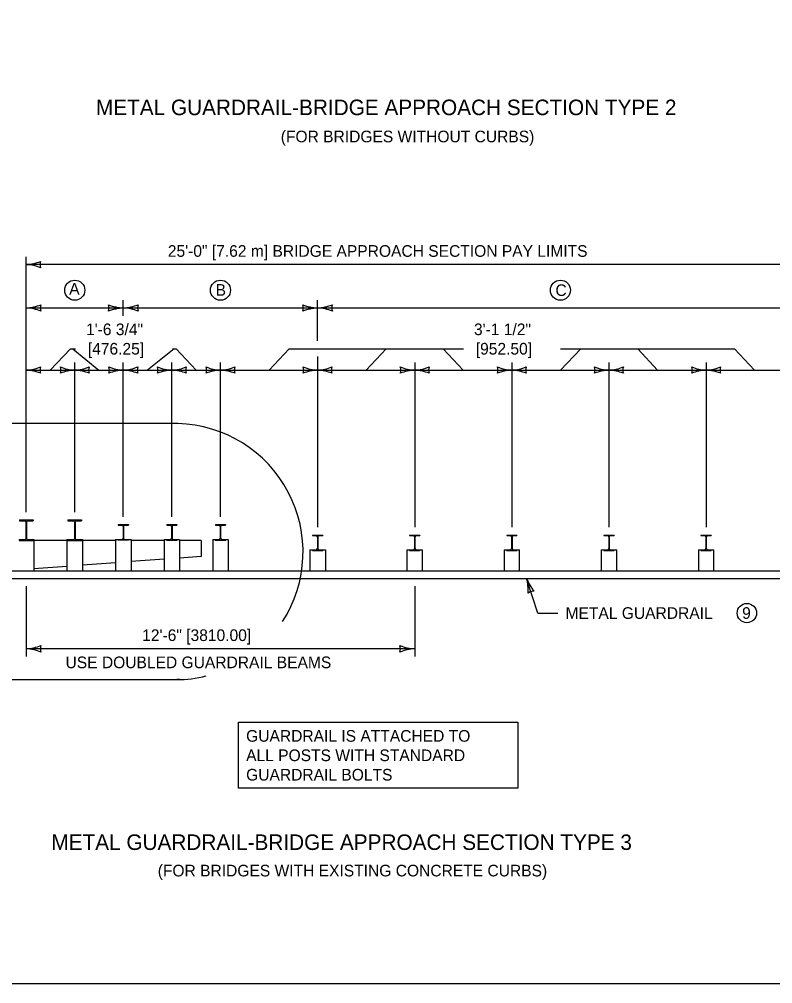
# Model space of a CAD drawing. Extents: x 49991.4 to 50021, y 49987.6 to 50011.4.
# Drawn here: x 50009.666 to 50013.547, y 49987.799 to 49992.766 of the extents above; entities that cross this region are included whole.
import ezdxf

# ---------------------------------------------------------------- set-up
doc = ezdxf.new("R2010")
doc.units = 0
for name, color, linetype in [('Level 1', 7, 'Continuous'), ('Level 2', 7, 'Continuous'), ('Level 3', 7, 'Continuous'), ('Level 4', 7, 'Continuous')]:
    doc.layers.add(name, color=color, linetype=linetype)

msp = doc.modelspace()

# ---------------------------------------------------------------- linework, layer by layer
at = {"layer": 'Level 1'}
for p, q in [((50009.6668, 49990.1875), (50009.7371, 49990.1875)), ((50009.6668, 49990.1875), (50009.6668, 49990.1822)), ((50009.7371, 49990.1875), (50009.7371, 49990.1822)), ((50009.9169, 49990.1875), (50009.9872, 49990.1875)), ((50009.9169, 49990.1875), (50009.9169, 49990.1822)), ((50009.9872, 49990.1875), (50009.9872, 49990.1822)), ((50009.6668, 49990.1822), (50009.6956, 49990.1822)), ((50009.7003, 49990.1775), (50009.7003, 49990.0908)), ((50009.7036, 49990.1775), (50009.7036, 49990.0908)), ((50009.7083, 49990.1822), (50009.7371, 49990.1822)), ((50009.9169, 49990.1822), (50009.9457, 49990.1822)), ((50009.9504, 49990.1775), (50009.9504, 49990.0908)), ((50009.9537, 49990.1775), (50009.9537, 49990.0908)), ((50009.9584, 49990.1822), (50009.9872, 49990.1822)), ((50010.1759, 49990.1633), (50010.2285, 49990.1633)), ((50010.1759, 49990.1633), (50010.1759, 49990.1604)), ((50010.1759, 49990.1604), (50010.1939, 49990.1604)), ((50010.2011, 49990.1533), (50010.2011, 49990.0932)), ((50010.2033, 49990.1533), (50010.2033, 49990.0932)), ((50010.2105, 49990.1604), (50010.2285, 49990.1604)), ((50010.2285, 49990.1633), (50010.2285, 49990.1604)), ((50010.4261, 49990.1633), (50010.4786, 49990.1633)), ((50010.4261, 49990.1633), (50010.4261, 49990.1604)), ((50010.4261, 49990.1604), (50010.4441, 49990.1604)), ((50010.4512, 49990.1533), (50010.4512, 49990.0932)), ((50010.4535, 49990.1533), (50010.4535, 49990.0932)), ((50010.4606, 49990.1604), (50010.4786, 49990.1604)), ((50010.4786, 49990.1633), (50010.4786, 49990.1604)), ((50010.6762, 49990.1633), (50010.7288, 49990.1633)), ((50010.6762, 49990.1633), (50010.6762, 49990.1604)), ((50010.6762, 49990.1604), (50010.6942, 49990.1604)), ((50010.7014, 49990.1533), (50010.7014, 49990.0932)), ((50010.7036, 49990.1533), (50010.7036, 49990.0932)), ((50010.7108, 49990.1604), (50010.7288, 49990.1604)), ((50010.7288, 49990.1633), (50010.7288, 49990.1604)), ((50009.6668, 49990.0808), (50009.6668, 49990.0861)), ((50009.6668, 49990.0861), (50009.6956, 49990.0861)), ((50009.7083, 49990.0861), (50009.7371, 49990.0861)), ((50009.7371, 49990.0808), (50009.7371, 49990.0861)), ((50009.7377, 49990.0808), (50009.7377, 49990.0861)), ((50009.7377, 49990.0861), (50009.742, 49990.0861)), ((50009.742, 49990.0861), (50009.742, 49989.9261)), ((50009.912, 49990.0861), (50009.912, 49989.9261)), ((50009.912, 49990.0861), (50009.9162, 49990.0861)), ((50009.9162, 49990.0808), (50009.9162, 49990.0861)), ((50009.9169, 49990.0808), (50009.9169, 49990.0861)), ((50009.9169, 49990.0861), (50009.9457, 49990.0861)), ((50009.9584, 49990.0861), (50009.9872, 49990.0861)), ((50009.9872, 49990.0808), (50009.9872, 49990.0861)), ((50009.9879, 49990.0808), (50009.9879, 49990.0861)), ((50009.9879, 49990.0861), (50009.9921, 49990.0861)), ((50009.9921, 49990.0861), (50009.9921, 49989.9261)), ((50010.1622, 49990.0861), (50010.1622, 49989.9261)), ((50010.1622, 49990.0861), (50010.1752, 49990.0861)), ((50010.1752, 49990.0832), (50010.1752, 49990.0861)), ((50010.2291, 49990.0832), (50010.1752, 49990.0832)), ((50010.1759, 49990.0832), (50010.1759, 49990.0861)), ((50010.1759, 49990.0861), (50010.1939, 49990.0861)), ((50010.2105, 49990.0861), (50010.2285, 49990.0861)), ((50010.2285, 49990.0832), (50010.2285, 49990.0861)), ((50010.2291, 49990.0832), (50010.2291, 49990.0861)), ((50010.2291, 49990.0861), (50010.2422, 49990.0861)), ((50010.2422, 49990.0861), (50010.2422, 49989.9261)), ((50010.4123, 49990.0861), (50010.4123, 49989.9261)), ((50010.4123, 49990.0861), (50010.4254, 49990.0861)), ((50010.4254, 49990.0832), (50010.4254, 49990.0861)), ((50010.4254, 49990.0832), (50010.4793, 49990.0832)), ((50010.4261, 49990.0832), (50010.4261, 49990.0861)), ((50010.4261, 49990.0861), (50010.4441, 49990.0861)), ((50010.4606, 49990.0861), (50010.4786, 49990.0861)), ((50010.4786, 49990.0832), (50010.4786, 49990.0861)), ((50010.4793, 49990.0832), (50010.4793, 49990.0861)), ((50010.4793, 49990.0861), (50010.4924, 49990.0861)), ((50010.4924, 49990.0861), (50010.4924, 49989.9261)), ((50010.6625, 49990.0861), (50010.6625, 49989.9261)), ((50010.6625, 49990.0861), (50010.6756, 49990.0861)), ((50010.6756, 49990.0832), (50010.6756, 49990.0861)), ((50010.6756, 49990.0832), (50010.7294, 49990.0832)), ((50010.6762, 49990.0832), (50010.6762, 49990.0861)), ((50010.6762, 49990.0861), (50010.6942, 49990.0861)), ((50010.7108, 49990.0861), (50010.7288, 49990.0861)), ((50010.7288, 49990.0832), (50010.7288, 49990.0861)), ((50010.7294, 49990.0832), (50010.7294, 49990.0861)), ((50010.7294, 49990.0861), (50010.7425, 49990.0861)), ((50010.7425, 49990.0861), (50010.7425, 49989.9261)), ((50011.1765, 49990.1099), (50011.229, 49990.1099)), ((50011.1765, 49990.1099), (50011.1765, 49990.1071)), ((50011.1765, 49990.1071), (50011.1945, 49990.1071)), ((50011.2016, 49990.0999), (50011.2016, 49990.0399)), ((50011.2039, 49990.0999), (50011.2039, 49990.0399)), ((50011.211, 49990.1071), (50011.229, 49990.1071)), ((50011.229, 49990.1099), (50011.229, 49990.1071)), ((50011.6767, 49990.1099), (50011.7293, 49990.1099)), ((50011.6767, 49990.1099), (50011.6767, 49990.1071)), ((50011.6767, 49990.1071), (50011.6948, 49990.1071)), ((50011.7019, 49990.0999), (50011.7019, 49990.0399)), ((50011.7042, 49990.0999), (50011.7042, 49990.0399)), ((50011.7113, 49990.1071), (50011.7293, 49990.1071)), ((50011.7293, 49990.1099), (50011.7293, 49990.1071)), ((50012.177, 49990.1099), (50012.2296, 49990.1099)), ((50012.177, 49990.1099), (50012.177, 49990.1071)), ((50012.177, 49990.1071), (50012.195, 49990.1071)), ((50012.2021, 49990.0999), (50012.2021, 49990.0399)), ((50012.2044, 49990.0999), (50012.2044, 49990.0399)), ((50012.2115, 49990.1071), (50012.2296, 49990.1071)), ((50012.2296, 49990.1099), (50012.2296, 49990.1071)), ((50012.6773, 49990.1099), (50012.7298, 49990.1099)), ((50012.6773, 49990.1099), (50012.6773, 49990.1071)), ((50012.6773, 49990.1071), (50012.6953, 49990.1071)), ((50012.7024, 49990.0999), (50012.7024, 49990.0399)), ((50012.7047, 49990.0999), (50012.7047, 49990.0399)), ((50012.7118, 49990.1071), (50012.7298, 49990.1071)), ((50012.7298, 49990.1099), (50012.7298, 49990.1071)), ((50013.1775, 49990.1099), (50013.2301, 49990.1099)), ((50013.1775, 49990.1099), (50013.1775, 49990.1071)), ((50013.1775, 49990.1071), (50013.1955, 49990.1071)), ((50013.2027, 49990.0999), (50013.2027, 49990.0399)), ((50013.2049, 49990.0999), (50013.2049, 49990.0399)), ((50013.2121, 49990.1071), (50013.2301, 49990.1071)), ((50013.2301, 49990.1099), (50013.2301, 49990.1071)), ((50009.6661, 49990.0808), (50009.7377, 49990.0808)), ((50009.912, 49990.0808), (50009.742, 49990.0808)), ((50009.9162, 49990.0808), (50009.9879, 49990.0808)), ((50010.1622, 49990.0808), (50009.9921, 49990.0808)), ((50010.4123, 49990.0808), (50010.2422, 49990.0808)), ((50010.6033, 49990.0808), (50010.4924, 49990.0808)), ((50010.6033, 49990.0808), (50010.6033, 49989.9994)), ((50010.4123, 49989.9853), (50010.2422, 49989.9727)), ((50010.6033, 49989.9994), (50010.4924, 49989.9912)), ((50011.1627, 49990.0328), (50011.1627, 49989.9261)), ((50011.1627, 49990.0328), (50011.1758, 49990.0328)), ((50011.1758, 49990.0299), (50011.1758, 49990.0328)), ((50011.1758, 49990.0299), (50011.2297, 49990.0299)), ((50011.1765, 49990.0299), (50011.1765, 49990.0328)), ((50011.1765, 49990.0328), (50011.1945, 49990.0328)), ((50011.211, 49990.0328), (50011.229, 49990.0328)), ((50011.229, 49990.0299), (50011.229, 49990.0328)), ((50011.2297, 49990.0299), (50011.2297, 49990.0328)), ((50011.2297, 49990.0328), (50011.2428, 49990.0328)), ((50011.2428, 49990.0328), (50011.2428, 49989.9261)), ((50011.663, 49990.0328), (50011.663, 49989.9261)), ((50011.663, 49990.0328), (50011.6761, 49990.0328)), ((50011.6761, 49990.0299), (50011.6761, 49990.0328)), ((50011.6761, 49990.0299), (50011.73, 49990.0299)), ((50011.6767, 49990.0299), (50011.6767, 49990.0328)), ((50011.6767, 49990.0328), (50011.6948, 49990.0328)), ((50011.7113, 49990.0328), (50011.7293, 49990.0328)), ((50011.7293, 49990.0299), (50011.7293, 49990.0328)), ((50011.73, 49990.0299), (50011.73, 49990.0328)), ((50011.73, 49990.0328), (50011.743, 49990.0328)), ((50011.743, 49989.9261), (50011.743, 49990.0328)), ((50012.1633, 49990.0328), (50012.1633, 49989.9261)), ((50012.1633, 49990.0328), (50012.1763, 49990.0328)), ((50012.1763, 49990.0299), (50012.1763, 49990.0328)), ((50012.1763, 49990.0299), (50012.2302, 49990.0299)), ((50012.177, 49990.0299), (50012.177, 49990.0328)), ((50012.177, 49990.0328), (50012.195, 49990.0328)), ((50012.2115, 49990.0328), (50012.2296, 49990.0328)), ((50012.2296, 49990.0299), (50012.2296, 49990.0328)), ((50012.2302, 49990.0299), (50012.2302, 49990.0328)), ((50012.2302, 49990.0328), (50012.2433, 49990.0328)), ((50012.2433, 49989.9261), (50012.2433, 49990.0328)), ((50012.6635, 49990.0328), (50012.6635, 49989.9261)), ((50012.6635, 49990.0328), (50012.6766, 49990.0328)), ((50012.6766, 49990.0299), (50012.6766, 49990.0328)), ((50012.6766, 49990.0299), (50012.7305, 49990.0299)), ((50012.6773, 49990.0299), (50012.6773, 49990.0328)), ((50012.6773, 49990.0328), (50012.6953, 49990.0328)), ((50012.7118, 49990.0328), (50012.7298, 49990.0328)), ((50012.7298, 49990.0299), (50012.7298, 49990.0328)), ((50012.7305, 49990.0299), (50012.7305, 49990.0328)), ((50012.7305, 49990.0328), (50012.7436, 49990.0328)), ((50012.7436, 49989.9261), (50012.7436, 49990.0328)), ((50013.1638, 49990.0328), (50013.1638, 49989.9261)), ((50013.1638, 49990.0328), (50013.1769, 49990.0328)), ((50013.1769, 49990.0299), (50013.1769, 49990.0328)), ((50013.1769, 49990.0299), (50013.2307, 49990.0299)), ((50013.1775, 49990.0299), (50013.1775, 49990.0328)), ((50013.1775, 49990.0328), (50013.1955, 49990.0328)), ((50013.2121, 49990.0328), (50013.2301, 49990.0328)), ((50013.2301, 49990.0299), (50013.2301, 49990.0328)), ((50013.2307, 49990.0299), (50013.2307, 49990.0328)), ((50013.2307, 49990.0328), (50013.2438, 49990.0328)), ((50013.2438, 49989.9261), (50013.2438, 49990.0328)), ((50009.912, 49989.9482), (50009.742, 49989.9356)), ((50010.1622, 49989.9667), (50009.9921, 49989.9541)), ((50008.8185, 49989.9261), (50013.9981, 49989.9261)), ((50008.8185, 49989.886), (50013.9981, 49989.886))]:
    msp.add_line(p, q, dxfattribs=at)
msp.add_lwpolyline([(49999.3835, 49998.9992), (50016.7501, 49998.9992), (50016.7501, 49987.7988), (49999.3835, 49987.7988)], close=True, dxfattribs=at)
msp.add_circle((50013.4138, 49989.7079), 0.05, dxfattribs=at)
for centre, radius, start, end in [((50009.6956, 49990.1775), 0.00467, 0, 90), ((50009.7083, 49990.1775), 0.00467, 90, 180), ((50009.9457, 49990.1775), 0.00467, 0, 90), ((50009.9584, 49990.1775), 0.00467, 90, 180), ((50010.1939, 49990.1533), 0.00714, 0, 90), ((50010.2105, 49990.1533), 0.00714, 90, 180), ((50010.4441, 49990.1533), 0.00714, 0, 90), ((50010.4606, 49990.1533), 0.00714, 90, 180), ((50010.6942, 49990.1533), 0.00714, 0, 90), ((50010.7108, 49990.1533), 0.00714, 90, 180), ((50009.6956, 49990.0908), 0.00467, 270, 0), ((50009.7083, 49990.0908), 0.00467, 180, 270), ((50009.9457, 49990.0908), 0.00467, 270, 0), ((50009.9584, 49990.0908), 0.00467, 180, 270), ((50010.1939, 49990.0932), 0.00714, 270, 0), ((50010.2105, 49990.0932), 0.00714, 180, 270), ((50010.4441, 49990.0932), 0.00714, 270, 0), ((50010.4606, 49990.0932), 0.00714, 180, 270), ((50010.6942, 49990.0932), 0.00714, 270, 0), ((50010.7108, 49990.0932), 0.00714, 180, 270), ((50011.1945, 49990.0999), 0.00714, 0, 90), ((50011.211, 49990.0999), 0.00714, 90, 180), ((50011.6948, 49990.0999), 0.00714, 0, 90), ((50011.7113, 49990.0999), 0.00714, 90, 180), ((50012.195, 49990.0999), 0.00714, 0, 90), ((50012.2115, 49990.0999), 0.00714, 90, 180), ((50012.6953, 49990.0999), 0.00714, 0, 90), ((50012.7118, 49990.0999), 0.00714, 90, 180), ((50013.1955, 49990.0999), 0.00714, 0, 90), ((50013.2121, 49990.0999), 0.00714, 90, 180), ((50011.1945, 49990.0399), 0.00714, 270, 0), ((50011.211, 49990.0399), 0.00714, 180, 270), ((50011.6948, 49990.0399), 0.00714, 270, 0), ((50011.7113, 49990.0399), 0.00714, 180, 270), ((50012.195, 49990.0399), 0.00714, 270, 0), ((50012.2115, 49990.0399), 0.00714, 180, 270), ((50012.6953, 49990.0399), 0.00714, 270, 0), ((50012.7118, 49990.0399), 0.00714, 180, 270), ((50013.1955, 49990.0399), 0.00714, 270, 0), ((50013.2121, 49990.0399), 0.00714, 180, 270)]:
    msp.add_arc(centre, radius, start, end, dxfattribs=at)
at = {"layer": 'Level 2'}
for p, q in [((50010.7948, 49988.8052), (50010.7948, 49989.1452)), ((50010.7948, 49989.1452), (50012.2345, 49989.1452)), ((50012.2345, 49989.1452), (50012.2345, 49988.8052)), ((50012.2345, 49988.8052), (50010.7948, 49988.8052))]:
    msp.add_line(p, q, dxfattribs=at)
for centre in [(50009.9521, 49991.3709), (50010.7025, 49991.3709), (50012.4534, 49991.3709)]:
    msp.add_circle(centre, 0.0517, dxfattribs=at)
at = {"layer": 'Level 3'}
for p, q in [((50009.702, 49990.2275), (50009.702, 49991.5426)), ((50014.6522, 49991.5026), (50009.702, 49991.5026)), ((50009.702, 49991.2792), (50010.2022, 49991.2792)), ((50010.2022, 49991.2392), (50010.2022, 49991.3192)), ((50010.2022, 49991.2792), (50011.2028, 49991.2792)), ((50011.2028, 49991.1092), (50011.2028, 49991.3192)), ((50011.2028, 49991.2792), (50013.7041, 49991.2792)), ((50009.9295, 49991.0692), (50009.8261, 49990.9592)), ((50009.9295, 49991.0692), (50009.9555, 49991.0692)), ((50009.9425, 49991.0692), (50010.0762, 49990.9592)), ((50010.4644, 49991.0692), (50010.327, 49990.9592)), ((50010.4551, 49991.0692), (50010.4737, 49991.0692)), ((50010.4737, 49991.0692), (50010.5771, 49990.9592)), ((50011.0559, 49991.0692), (50010.9526, 49990.9592)), ((50011.0559, 49991.0692), (50011.4417, 49991.0692)), ((50011.2027, 49991.0292), (50011.2027, 49990.1499)), ((50011.4417, 49991.0692), (50011.9536, 49991.0692)), ((50011.5562, 49991.0692), (50011.4529, 49990.9592)), ((50011.8497, 49991.0692), (50011.9531, 49990.9592)), ((50012.4532, 49991.0692), (50012.741, 49991.0692)), ((50012.5585, 49991.0692), (50012.4534, 49990.9592)), ((50012.741, 49991.0692), (50013.3501, 49991.0692)), ((50012.8517, 49991.0692), (50012.9537, 49990.9592)), ((50013.3501, 49991.0692), (50013.4535, 49990.9592)), ((50009.9521, 49990.2275), (50009.9521, 49990.9992)), ((50010.2022, 49990.2033), (50010.2022, 49990.9992)), ((50010.4524, 49990.2033), (50010.4523, 49990.9992)), ((50010.7025, 49990.2033), (50010.7024, 49990.9992)), ((50011.703, 49990.9992), (50011.703, 49990.1499)), ((50012.2033, 49990.9992), (50012.2033, 49990.1499)), ((50012.7035, 49990.9992), (50012.7035, 49990.1499)), ((50013.2038, 49990.9992), (50013.2038, 49990.1499)), ((50009.702, 49990.9592), (50013.7041, 49990.9592)), ((50012.3374, 49989.7079), (50012.2794, 49989.886)), ((50009.702, 49989.8461), (50009.702, 49989.4839)), ((50011.7031, 49989.8461), (50011.7031, 49989.4839)), ((50012.3374, 49989.7079), (50012.4398, 49989.7079)), ((50011.7031, 49989.5239), (50009.702, 49989.5239))]:
    msp.add_line(p, q, dxfattribs=at)
for centre, radius, start, end in [((50009.6908, 49991.7295), 0.2271, 272.8273, 292.0772), ((50009.693, 49991.2861), 0.2167, 67.456, 87.6395), ((50009.8269, 49991.5026), 0.0534, 162.1388, 197.8612), ((50009.6905, 49991.512), 0.2331, 272.8273, 292.0772), ((50009.6928, 49991.0569), 0.2224, 67.456, 87.6395), ((50009.8302, 49991.2792), 0.0548, 162.1388, 197.8612), ((50010.2114, 49991.5014), 0.2224, 247.456, 267.6395), ((50010.0739, 49991.2792), 0.0548, 342.1388, 17.8612), ((50010.2137, 49991.0463), 0.2331, 92.8273, 112.0772), ((50010.1907, 49991.512), 0.2331, 272.8273, 292.0772), ((50010.1931, 49991.0569), 0.2224, 67.456, 87.6395), ((50010.3305, 49991.2792), 0.0548, 162.1388, 197.8612), ((50011.212, 49991.5014), 0.2224, 247.456, 267.6395), ((50011.0745, 49991.2792), 0.0548, 342.1388, 17.8612), ((50011.2143, 49991.0463), 0.2331, 92.8273, 112.0772), ((50011.1913, 49991.512), 0.2331, 272.8273, 292.0772), ((50011.1936, 49991.0569), 0.2224, 67.456, 87.6395), ((50011.3311, 49991.2792), 0.0548, 162.1388, 197.8612), ((50009.6908, 49991.186), 0.2271, 272.8273, 292.0772), ((50009.693, 49990.7426), 0.2167, 67.456, 87.6395), ((50009.8269, 49990.9592), 0.0534, 162.1388, 197.8612), ((50009.961, 49991.1757), 0.2167, 247.456, 267.6395), ((50009.8271, 49990.9592), 0.0534, 342.1388, 17.8612), ((50009.9633, 49990.7323), 0.2271, 92.8273, 112.0772), ((50009.9409, 49991.186), 0.2271, 272.8273, 292.0772), ((50009.9432, 49990.7426), 0.2167, 67.456, 87.6395), ((50010.0771, 49990.9592), 0.0534, 162.1388, 197.8612), ((50010.2111, 49991.1757), 0.2167, 247.456, 267.6395), ((50010.0772, 49990.9592), 0.0534, 342.1388, 17.8612), ((50010.2134, 49990.7323), 0.2271, 92.8273, 112.0772), ((50010.191, 49991.186), 0.2271, 272.8273, 292.0772), ((50010.1933, 49990.7426), 0.2167, 67.456, 87.6395), ((50010.3272, 49990.9592), 0.0534, 162.1388, 197.8612), ((50010.4612, 49991.1757), 0.2167, 247.456, 267.6395), ((50010.3273, 49990.9592), 0.0534, 342.1388, 17.8612), ((50010.4635, 49990.7323), 0.2271, 92.8273, 112.0772), ((50010.4411, 49991.186), 0.2271, 272.8273, 292.0772), ((50010.4434, 49990.7426), 0.2167, 67.456, 87.6395), ((50010.5773, 49990.9592), 0.0534, 162.1388, 197.8612), ((50010.7114, 49991.1757), 0.2167, 247.456, 267.6395), ((50010.5775, 49990.9592), 0.0534, 342.1388, 17.8612), ((50010.7136, 49990.7323), 0.2271, 92.8273, 112.0772), ((50010.6912, 49991.186), 0.2271, 272.8273, 292.0772), ((50010.6935, 49990.7426), 0.2167, 67.456, 87.6395), ((50010.8274, 49990.9592), 0.0534, 162.1388, 197.8612), ((50011.2117, 49991.1757), 0.2167, 247.456, 267.6395), ((50011.0778, 49990.9592), 0.0534, 342.1388, 17.8612), ((50011.2139, 49990.7323), 0.2271, 92.8273, 112.0772), ((50011.1915, 49991.186), 0.2271, 272.8273, 292.0772), ((50011.1938, 49990.7426), 0.2167, 67.456, 87.6395), ((50011.3277, 49990.9592), 0.0534, 162.1388, 197.8612), ((50011.7119, 49991.1757), 0.2167, 247.456, 267.6395), ((50011.578, 49990.9592), 0.0534, 342.1388, 17.8612), ((50011.7142, 49990.7323), 0.2271, 92.8273, 112.0772), ((50011.6918, 49991.186), 0.2271, 272.8273, 292.0772), ((50011.6941, 49990.7426), 0.2167, 67.456, 87.6395), ((50011.828, 49990.9592), 0.0534, 162.1388, 197.8612), ((50012.2122, 49991.1757), 0.2167, 247.456, 267.6395), ((50012.0783, 49990.9592), 0.0534, 342.1388, 17.8612), ((50012.2145, 49990.7323), 0.2271, 92.8273, 112.0772), ((50012.1921, 49991.186), 0.2271, 272.8273, 292.0772), ((50012.1943, 49990.7426), 0.2167, 67.456, 87.6395), ((50012.3283, 49990.9592), 0.0534, 162.1388, 197.8612), ((50012.7125, 49991.1757), 0.2167, 247.456, 267.6395), ((50012.5786, 49990.9592), 0.0534, 342.1388, 17.8612), ((50012.7147, 49990.7323), 0.2271, 92.8273, 112.0772), ((50012.6923, 49991.186), 0.2271, 272.8273, 292.0772), ((50012.6946, 49990.7426), 0.2167, 67.456, 87.6395), ((50012.8285, 49990.9592), 0.0534, 162.1388, 197.8612), ((50013.2127, 49991.1757), 0.2167, 247.456, 267.6395), ((50013.0788, 49990.9592), 0.0534, 342.1388, 17.8612), ((50013.215, 49990.7323), 0.2271, 92.8273, 112.0772), ((50013.1926, 49991.186), 0.2271, 272.8273, 292.0772), ((50013.1949, 49990.7426), 0.2167, 67.456, 87.6395), ((50013.3288, 49990.9592), 0.0534, 162.1388, 197.8612), ((50012.0708, 49989.8275), 0.2167, 355.4765, 15.66), ((50012.4917, 49989.9669), 0.2271, 200.8478, 220.0976), ((50012.3181, 49989.7672), 0.0534, 90.1593, 125.8816), ((50009.6905, 49989.7567), 0.2331, 272.8273, 292.0772), ((50009.8303, 49989.5239), 0.0548, 162.1388, 197.8612), ((50011.7123, 49989.7461), 0.2224, 247.456, 267.6395), ((50011.5748, 49989.5239), 0.0548, 342.1388, 17.8612), ((50009.6928, 49989.3016), 0.2224, 67.456, 87.6395), ((50011.7146, 49989.2911), 0.2331, 92.8273, 112.0772)]:
    msp.add_arc(centre, radius, start, end, dxfattribs=at)
at = {"layer": 'Level 4'}
for p, q in [((50010.4837, 49990.6834), (50009.294, 49990.6834)), ((50009.3032, 49989.3649), (50010.4928, 49989.3649)), ((50010.4928, 49989.3649), (50010.4779, 49989.3649))]:
    msp.add_line(p, q, dxfattribs=at)
for centre, radius, start, end in [((50010.4666, 49990.0221), 0.6615, 327.2111, 88.5245), ((50010.4779, 49989.9745), 0.6096, 270, 284.3518)]:
    msp.add_arc(centre, radius, start, end, dxfattribs=at)

# ---------------------------------------------------------------- texts
at = {"layer": 'Level 2'}
for s, height, p in [('METAL GUARDRAIL-BRIDGE APPROACH SECTION TYPE 2', 0.08, (50010.0612, 49992.2724)), ('(FOR BRIDGES WITHOUT CURBS)', 0.06, (50011.0131, 49992.1324)), ('25\'-0" [7.62 m] BRIDGE APPROACH SECTION PAY LIMITS', 0.06, (50010.4315, 49991.5427)), ('A', 0.06, (50009.9235, 49991.3479)), ('B', 0.06, (50010.6777, 49991.3422)), ('C', 0.06, (50012.4279, 49991.3409)), ('1\'-6 3/4"', 0.06, (50010.0101, 49991.1392)), ('3\'-1 1/2"', 0.06, (50012.0082, 49991.1392)), ('[476.25]', 0.06, (50010.0194, 49991.0392)), ('[952.50]', 0.06, (50012.0175, 49991.0392)), ('METAL GUARDRAIL', 0.06, (50012.4798, 49989.6779)), ('9', 0.06, (50013.3893, 49989.6779)), ('12\'-6" [3810.00]', 0.06, (50010.2995, 49989.5639)), ('USE DOUBLED GUARDRAIL BEAMS', 0.06, (50009.9046, 49989.4239)), ('GUARDRAIL IS ATTACHED TO', 0.06, (50010.8348, 49989.0452)), ('ALL POSTS WITH STANDARD', 0.06, (50010.8348, 49988.9452)), ('GUARDRAIL BOLTS', 0.06, (50010.8348, 49988.8452)), ('METAL GUARDRAIL-BRIDGE APPROACH SECTION TYPE 3', 0.08, (50009.8317, 49988.4877)), ('(FOR BRIDGES WITH EXISTING CONCRETE CURBS)', 0.06, (50010.3794, 49988.3514))]:
    msp.add_text(s, height=height, dxfattribs=at).set_placement(p)

doc.saveas('drawing.dxf')
